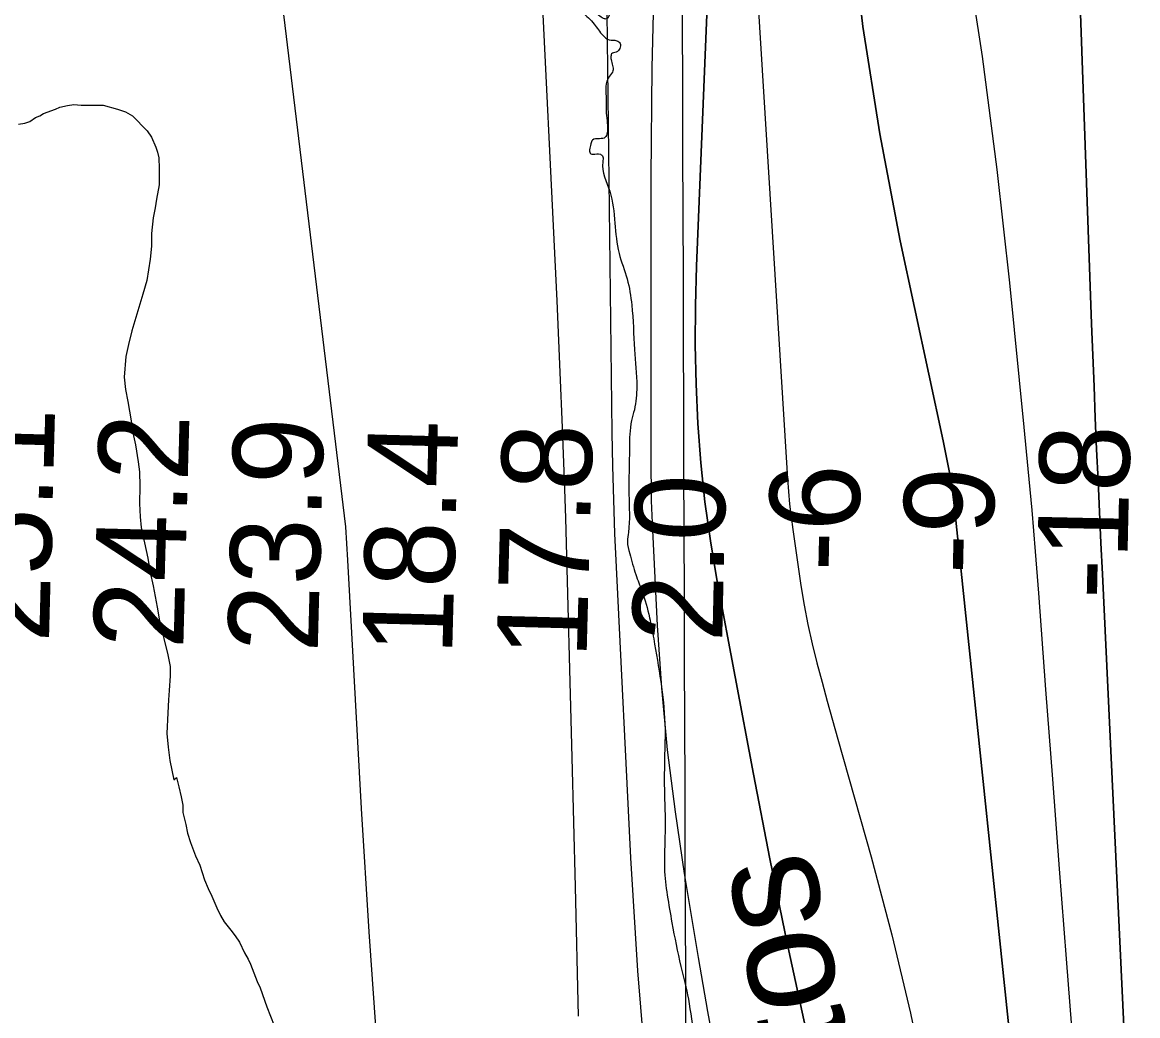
# Model space of a CAD drawing. Extents: x 3392644 to 3430565, y 576657 to 602123.
# Drawn here: x 3401526 to 3402355, y 590935 to 591674 of the extents above; entities that cross this region are included whole.
import ezdxf

# ---------------------------------------------------------------- set-up
doc = ezdxf.new("R2010")
doc.units = 0
for name, color, linetype in [('V-GRID-MAJR', 7, 'Continuous'), ('V-RIVR-EDGE', 7, 'Continuous'), ('V-RIVR-IDEN', 7, 'Continuous'), ('V-RIVR-RANG', 7, 'Continuous'), ('V-SITE-VEGE', 7, 'Continuous'), ('V-TOPO-DPTH', 7, 'Continuous'), ('V-TOPO-MINR', 7, 'Continuous'), ('V-TOPO-WATR', 7, 'Continuous')]:
    doc.layers.add(name, color=color, linetype=linetype)

msp = doc.modelspace()

# ---------------------------------------------------------------- linework, layer by layer
at = {"layer": 'V-GRID-MAJR'}
msp.add_spline([(3402048.6720000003, 582063.4890000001), (3402028.4020000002, 588122.6730000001), (3402008.125, 594183.791), (3401987.849, 600244.93), (3401987.843, 600246.845)], degree=3, dxfattribs=at)
at = {"layer": 'V-RIVR-EDGE'}
msp.add_spline([(3401987.9213314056, 591815.3849305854), (3401986.374240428, 591794.2696732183), (3401984.9403506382, 591784.4067082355), (3401983.8640619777, 591776.657111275), (3401978.9012120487, 591764.6886201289), (3401977.1132064, 591754.1217800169), (3401973.567691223, 591745.3211626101), (3401971.4360255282, 591738.2789260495), (3401969.6454059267, 591726.6549662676), (3401969.2668931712, 591716.0846408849), (3401969.2590513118, 591712.9132818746), (3401968.1827626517, 591705.1636849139), (3401965.688267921, 591693.8938409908), (3401962.838786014, 591681.5677487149), (3401961.7755671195, 591679.1037501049), (3401961.420579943, 591678.0475017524), (3401960.3608463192, 591676.9929960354), (3401957.895105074, 591677.351468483), (3401951.2113409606, 591681.9488754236), (3401944.5240915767, 591685.1367894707), (3401941.7051057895, 591685.1437600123), (3401942.052251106, 591683.0286493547), (3401946.620033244, 591677.7317238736), (3401950.8371847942, 591673.1404161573), (3401957.5113644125, 591664.6669037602), (3401962.0843744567, 591661.4842176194), (3401967.720603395, 591660.7655300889), (3401970.1819880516, 591658.6451915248), (3401967.3473185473, 591652.309444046), (3401963.8201010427, 591650.9086643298), (3401963.465113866, 591649.8524159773), (3401963.457272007, 591646.681056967), (3401964.845853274, 591638.2206143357), (3401962.369656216, 591634.3506081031), (3401959.531501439, 591626.6053677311), (3401959.5245308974, 591623.7863819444), (3401959.849893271, 591612.8619407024), (3401959.83508087, 591606.8715959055), (3401960.503231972, 591592.0701778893), (3401959.085897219, 591588.9023041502), (3401954.8548045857, 591587.8556402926), (3401949.5665922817, 591586.8115903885), (3401948.5025020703, 591583.995218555), (3401948.4842043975, 591576.5953808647), (3401949.8928259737, 591576.2395223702), (3401955.530797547, 591576.2255812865), (3401957.2883070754, 591574.4593585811), (3401957.27872258, 591570.5832531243), (3401962.5102992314, 591548.7230435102), (3401966.3280264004, 591525.1044530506), (3401969.443621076, 591502.5447248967), (3401975.3869147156, 591483.5017584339), (3401978.862724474, 591464.112517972), (3401980.895059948, 591430.9842070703), (3401982.5889632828, 591403.4947390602), (3401980.7844025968, 591386.2328077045), (3401978.650122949, 591378.1334514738), (3401977.190093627, 591357.6992897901), (3401976.752331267, 591323.1675852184), (3401976.330252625, 591294.9785986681), (3401975.6089511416, 591288.2852500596), (3401977.3481629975, 591279.1191896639), (3401981.890676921, 591263.6034407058), (3401986.4410327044, 591251.2590507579), (3401992.0302104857, 591231.5122091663), (3401995.162360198, 591215.6475722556), (3402000.3695399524, 591183.9209123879), (3402003.4642230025, 591152.904226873), (3402003.0177474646, 591114.8487900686), (3402003.616193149, 591071.8575141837), (3402003.1975997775, 591045.0780205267), (3402005.2621740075, 591024.987518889), (3402008.735369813, 591004.5411587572), (3402015.3502998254, 590972.1062671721), (3402020.9281504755, 590947.7785736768), (3402026.4946739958, 590918.8700282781), (3402035.9503727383, 590895.2374967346), (3402040.4928866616, 590879.7217477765), (3402044.68738395, 590865.968736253), (3402045.0005478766, 590850.1110698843), (3402048.467644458, 590827.198097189), (3402058.6080493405, 590795.4592388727), (3402062.094314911, 590780.2984770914), (3402068.73364182, 590757.7300357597), (3402076.0733585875, 590733.3979856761), (3402090.056758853, 590688.2593603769), (3402093.19849306, 590676.2708289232), (3402097.73490776, 590658.2884674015), (3402098.0637554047, 590648.7735190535), (3402100.858344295, 590638.9000982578), (3402105.0606834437, 590628.3184457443)], degree=3, dxfattribs=at)
at = {"layer": 'V-SITE-VEGE'}
for points in [[(3401522.7260000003, 591598.542), (3401527.389, 591599.414), (3401531.129, 591600.7660000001), (3401535.352, 591603.508), (3401538.625, 591604.866), (3401541.4390000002, 591606.691), (3401550.319, 591609.845), (3401553.591, 591611.201), (3401559.193, 591612.53), (3401563.8540000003, 591613.404), (3401569.435, 591612.872), (3401585.72, 591612.675), (3401596.3910000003, 591609.757), (3401602.416, 591607.821), (3401607.501, 591604.968), (3401618.534, 591593.6680000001), (3401621.735, 591588.976), (3401624.903, 591581.49), (3401626.252, 591577.753), (3401627.133, 591573.552), (3401627.504, 591565.637), (3401627.358, 591553.539), (3401625.3680000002, 591542.861), (3401624.358, 591536.356), (3401622.873, 591528.928), (3401621.802, 591517.308), (3401621.6920000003, 591508.002), (3401620.643, 591498.241), (3401618.13, 591482.451), (3401615.2120000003, 591472.248), (3401606.973, 591444.889), (3401604.521, 591434.681), (3401602.555, 591425.863), (3401601.441, 591410.519), (3401602.258, 591401.201), (3401604.0130000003, 591392.339), (3401606.633, 591377.878), (3401607.923, 591369.025), (3401609.676, 591360.161), (3401611.853, 591347.5700000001), (3401612.693, 591340.113), (3401613.031, 591329.406), (3401612.873, 591316.377), (3401613.221, 591306.602), (3401614.057, 591298.68), (3401618.9, 591275.818), (3401620.6350000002, 591265.095), (3401622.843, 591255.295), (3401625.9080000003, 591239.435), (3401627.647, 591229.177), (3401633.861, 591203.9720000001), (3401635.614, 591195.11), (3401635.532, 591188.133), (3401634.938, 591177.432), (3401634.387, 591170.459), (3401633.805, 591160.694), (3401633.154, 591145.344), (3401633.961, 591135.098), (3401635.241, 591125.308), (3401638.325, 591110.845), (3401640.208, 591112.687), (3401641.983, 591105.682), (3401643.757, 591098.215)], [(3401643.757, 591098.215), (3401645.08, 591092.149), (3401645.012, 591086.566), (3401647.232, 591077.697), (3401648.551, 591071.165), (3401650.794, 591064.159), (3401654.398, 591054.343), (3401657.572, 591047.3250000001), (3401661.167, 591036.579), (3401663.878, 591030.029), (3401666.6040000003, 591024.414), (3401670.221, 591015.527), (3401672.9450000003, 591009.91), (3401675.681, 591005.224), (3401680.725, 590999.113), (3401683.932, 590994.888), (3401687.131, 590990.194), (3401690.7600000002, 590982.2390000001), (3401693.4960000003, 590977.553), (3401695.313, 590973.808), (3401700.275, 590960.721), (3401702.5470000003, 590956.039), (3401707.497, 590942.017), (3401712.912, 590927.992)]]:
    msp.add_lwpolyline(points, dxfattribs=at)
at = {"layer": 'V-TOPO-DPTH'}
for points in [[(3402200.914730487, 592946.7586107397), (3402085.380665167, 592338.7008568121), (3402052.7727680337, 592069.1801388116), (3402051.4005930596, 592056.587293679), (3402050.2280213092, 592043.9782718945), (3402049.354854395, 592031.3449851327), (3402048.6812907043, 592018.6955217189), (3402026.940177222, 591493.0218269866), (3402026.170554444, 591463.746747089), (3402025.9881179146, 591434.4768427), (3402026.6864607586, 591405.2147015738), (3402027.971989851, 591375.9577359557), (3402030.2512651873, 591346.7724878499), (3402033.264669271, 591317.6773761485), (3402037.379266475, 591288.7174690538), (3402042.2279924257, 591259.8476983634), (3402069.3611059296, 591115.1590404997), (3402081.620996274, 591052.1971110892), (3402094.4613117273, 590989.3579844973), (3402108.172264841, 590926.7030621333)], [(3402108.172264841, 590926.7030621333), (3402094.4613117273, 590989.3579844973), (3402081.620996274, 591052.1971110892), (3402069.3611059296, 591115.1590404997), (3402042.2279924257, 591259.8476983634), (3402037.379266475, 591288.7174690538), (3402033.264669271, 591317.6773761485), (3402030.2512651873, 591346.7724878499), (3402027.971989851, 591375.9577359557), (3402026.6864607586, 591405.2147015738), (3402025.9881179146, 591434.4768427), (3402026.170554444, 591463.746747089), (3402026.940177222, 591493.0218269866), (3402048.6812907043, 592018.6955217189), (3402049.354854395, 592031.3449851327), (3402050.2280213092, 592043.9782718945), (3402051.4005930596, 592056.587293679), (3402052.7727680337, 592069.1801388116), (3402085.380665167, 592338.7008568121), (3402200.914730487, 592946.7586107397)], [(3402006.5459997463, 592495.9372565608), (3401995.6325773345, 592392.0817369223), (3401964.145147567, 592062.9417480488), (3401963.62457059, 592056.7870882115), (3401963.194334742, 592050.6271157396), (3401962.8996105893, 592044.4591743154), (3401962.695227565, 592038.2859202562), (3401960.711910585, 591948.5655973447), (3401959.843778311, 591897.526860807), (3401959.3223328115, 591846.4863485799), (3401959.3209174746, 591795.4431728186), (3401959.6661889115, 591744.3982213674), (3401964.115790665, 591369.1838692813), (3401964.554176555, 591344.122876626), (3401965.1806947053, 591319.0676487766), (3401966.089411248, 591294.0210681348), (3401967.186260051, 591268.9802522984), (3401977.8742352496, 591052.8318883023), (3401983.2324119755, 590968.6679456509), (3401990.1753502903, 590884.6576055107)], [(3402302.6134252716, 591961.063061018), (3402320.8567761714, 591450.0387901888), (3402321.7186690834, 591426.7553938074), (3402322.6214168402, 591403.4736354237), (3402323.585446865, 591380.1943340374), (3402324.590331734, 591356.9166706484), (3402325.635093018, 591333.640658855), (3402326.6921673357, 591310.3652111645), (3402327.767711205, 591287.0906096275), (3402328.8555681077, 591263.8165721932), (3402355.1042787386, 590706.9785494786)], [(3402355.1042787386, 590706.9785494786), (3402328.8555681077, 591263.8165721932), (3402327.767711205, 591287.0906096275), (3402326.6921673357, 591310.3652111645), (3402325.635093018, 591333.640658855), (3402324.590331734, 591356.9166706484), (3402323.585446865, 591380.1943340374), (3402322.6214168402, 591403.4736354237), (3402321.7186690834, 591426.7553938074), (3402320.8567761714, 591450.0387901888), (3402302.6134252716, 591961.063061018)], [(3402266.7923190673, 590856.0167946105), (3402219.383289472, 591308.7931476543), (3402219.16029798, 591310.8708115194), (3402218.6892060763, 591315.0232906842), (3402218.441105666, 591317.0981059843), (3402217.6872916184, 591323.2664710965), (3402217.019515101, 591328.2719567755), (3402216.2784868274, 591333.2657462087), (3402215.427580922, 591338.2419912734), (3402214.503423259, 591343.2065400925), (3402213.5120709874, 591348.1597933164), (3402212.5044609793, 591353.1096953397), (3402211.472464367, 591358.0545705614), (3402210.4242100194, 591362.9960945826), (3402178.4663359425, 591511.8390599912), (3402163.293924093, 591591.4518484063), (3402150.5984855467, 591671.3993649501), (3402141.618506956, 591751.8489736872)], [(3402266.7923190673, 590856.0167946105), (3402219.383289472, 591308.7931476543), (3402219.16029798, 591310.8708115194), (3402218.6892060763, 591315.0232906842), (3402218.441105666, 591317.0981059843), (3402217.6872916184, 591323.2664710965), (3402217.019515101, 591328.2719567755), (3402216.2784868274, 591333.2657462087), (3402215.427580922, 591338.2419912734), (3402214.503423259, 591343.2065400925), (3402213.5120709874, 591348.1597933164), (3402212.5044609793, 591353.1096953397), (3402211.472464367, 591358.0545705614), (3402210.4242100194, 591362.9960945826), (3402178.4663359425, 591511.8390599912), (3402163.293924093, 591591.4518484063), (3402150.5984855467, 591671.3993649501), (3402141.618506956, 591751.8489736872)]]:
    msp.add_lwpolyline(points, dxfattribs=at)
at = {"layer": 'V-TOPO-MINR'}
for points in [[(3402166.3477562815, 592989.6805613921), (3402023.333321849, 592106.6881891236), (3402019.3003042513, 592076.6578368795), (3402015.7437181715, 592046.5768775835), (3402012.9017793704, 592016.4200077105), (3402010.536272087, 591986.2125307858), (3402003.773892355, 591884.3399300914), (3401999.196925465, 591803.1313316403), (3401995.7015482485, 591721.8870109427), (3401993.828555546, 591640.5891068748), (3401993.0371525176, 591559.2554805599), (3401993.092471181, 591340.1100279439), (3401993.178405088, 591329.2430207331), (3401993.3751991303, 591318.3788706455), (3401993.7382833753, 591307.5190062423), (3401994.212227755, 591296.6619989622), (3401997.8585246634, 591225.6198225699), (3402001.02583153, 591179.3292255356), (3402005.2396910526, 591133.1521294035), (3402011.0233795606, 591087.1452846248), (3402017.8536207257, 591041.251940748), (3402028.254734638, 590978.702703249), (3402035.2523009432, 590938.4310933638), (3402042.638547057, 590898.2338251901)], [(3402006.5459997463, 592495.9372565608), (3401995.6325773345, 592392.0817369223), (3401964.145147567, 592062.9417480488), (3401963.62457059, 592056.7870882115), (3401963.194334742, 592050.6271157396), (3401962.8996105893, 592044.4591743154), (3401962.695227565, 592038.2859202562), (3401960.711910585, 591948.5655973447), (3401959.843778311, 591897.526860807), (3401959.3223328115, 591846.4863485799), (3401959.3209174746, 591795.4431728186), (3401959.6661889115, 591744.3982213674), (3401964.115790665, 591369.1838692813), (3401964.554176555, 591344.122876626), (3401965.1806947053, 591319.0676487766), (3401966.089411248, 591294.0210681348), (3401967.186260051, 591268.9802522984), (3401977.8742352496, 591052.8318883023), (3401983.2324119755, 590968.6679456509), (3401990.1753502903, 590884.6576055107)], [(3401675.8207681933, 592029.1044409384), (3401676.406682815, 592025.2731897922), (3401676.5253450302, 592024.6206556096), (3401677.980705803, 592016.4691087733), (3401679.401175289, 592008.3116014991), (3401680.7693078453, 592000.1451535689), (3401682.1025491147, 591991.9727452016), (3401765.8551486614, 591299.0722258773), (3401767.3352383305, 591274.288312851), (3401777.6937299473, 591089.6539216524), (3401783.3508998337, 590997.885167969), (3401789.683309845, 590906.1667832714)], [(3401896.8283169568, 592004.9982508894), (3401923.1078588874, 591467.2142838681), (3401924.442691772, 591437.7584688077), (3401925.6859397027, 591408.2986460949), (3401926.868130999, 591378.8361516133), (3401928.5903850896, 591334.1815834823), (3401928.8526208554, 591327.0439458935), (3401929.0974771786, 591319.9057439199), (3401929.316264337, 591312.7666953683), (3401929.517672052, 591305.6270824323), (3401934.2166814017, 591127.5169230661), (3401936.680185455, 591031.3200367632), (3401939.044525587, 590935.1207899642)], [(3402302.6134252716, 591961.063061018), (3402320.8567761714, 591450.0387901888), (3402321.7186690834, 591426.7553938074), (3402322.6214168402, 591403.4736354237), (3402323.585446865, 591380.1943340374), (3402324.590331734, 591356.9166706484), (3402325.635093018, 591333.640658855), (3402326.6921673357, 591310.3652111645), (3402327.767711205, 591287.0906096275), (3402328.8555681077, 591263.8165721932), (3402355.1042787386, 590706.9785494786)], [(3402066.314073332, 591791.0766759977), (3402094.6532840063, 591334.8446766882), (3402095.357867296, 591325.3870916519), (3402096.217392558, 591315.9455394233), (3402097.3093307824, 591306.528036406), (3402098.55621098, 591297.1265661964), (3402104.615588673, 591255.3924102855), (3402106.989970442, 591240.8788731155), (3402109.709146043, 591226.4366919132), (3402112.945512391, 591212.101544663), (3402116.526672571, 591197.8377533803), (3402120.3902417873, 591183.6340001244), (3402124.284529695, 591169.4387277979), (3402128.224895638, 591155.2561768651), (3402132.1959802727, 591141.0821068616), (3402156.8271223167, 591053.7120508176), (3402172.1772098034, 590995.6444052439), (3402186.2509795, 590937.2909226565), (3402198.410272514, 590878.5086845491)], [(3402141.618506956, 591751.8489736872), (3402150.5984855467, 591671.3993649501), (3402163.293924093, 591591.4518484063), (3402178.4663359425, 591511.8390599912), (3402210.4242100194, 591362.9960945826), (3402211.472464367, 591358.0545705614), (3402212.5044609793, 591353.1096953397), (3402213.5120709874, 591348.1597933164), (3402214.503423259, 591343.2065400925), (3402215.427580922, 591338.2419912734), (3402216.2784868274, 591333.2657462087), (3402217.019515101, 591328.2719567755), (3402217.6872916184, 591323.2664710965), (3402218.441105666, 591317.0981059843), (3402218.6892060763, 591315.0232906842), (3402219.16029798, 591310.8708115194), (3402219.383289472, 591308.7931476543), (3402266.7923190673, 590856.0167946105)], [(3402226.428971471, 591732.9130582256), (3402239.400671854, 591649.0591442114), (3402250.280920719, 591564.9083029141), (3402259.7668685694, 591480.5595100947), (3402270.4937692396, 591373.1503454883), (3402273.453070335, 591342.3473431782), (3402276.2577657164, 591311.530855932), (3402278.830552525, 591280.6941412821), (3402281.2487336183, 591249.8439416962), (3402286.604579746, 591178.0507601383), (3402291.6250183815, 591111.2969430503), (3402296.699195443, 591044.5472436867), (3402301.853980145, 590977.8037209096), (3402307.062503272, 590911.0643158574)]]:
    msp.add_lwpolyline(points, dxfattribs=at)
at = {"layer": 'V-TOPO-WATR'}
msp.add_lwpolyline([(3402200.914730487, 592946.7586107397), (3402085.380665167, 592338.7008568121), (3402052.7727680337, 592069.1801388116), (3402051.4005930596, 592056.587293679), (3402050.2280213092, 592043.9782718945), (3402049.354854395, 592031.3449851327), (3402048.6812907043, 592018.6955217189), (3402026.940177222, 591493.0218269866), (3402026.170554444, 591463.746747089), (3402025.9881179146, 591434.4768427), (3402026.6864607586, 591405.2147015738), (3402027.971989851, 591375.9577359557), (3402030.2512651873, 591346.7724878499), (3402033.264669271, 591317.6773761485), (3402037.379266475, 591288.7174690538), (3402042.2279924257, 591259.8476983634), (3402069.3611059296, 591115.1590404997), (3402081.620996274, 591052.1971110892), (3402094.4613117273, 590989.3579844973), (3402108.172264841, 590926.7030621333)], dxfattribs=at)

# ---------------------------------------------------------------- texts
at = {"layer": 'V-RIVR-IDEN'}
msp.add_text('Photos', height=83, rotation=101.0107529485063, dxfattribs=at).set_placement((3402178.038564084, 590721.1296090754))
at = {"layer": 'V-RIVR-RANG'}
for s, height, rotation, p in [('25.1', 67, 88.47832571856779, (3401545.370116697, 591212.6836548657)), ('24.2', 67, 88.47832571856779, (3401645.2780744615, 591207.9094763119)), ('23.9', 67, 88.47832571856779, (3401745.2430697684, 591205.2447898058)), ('18.4', 67, 88.47832571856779, (3401845.2210744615, 591203.1064763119)), ('17.8', 67, 88.47832571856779, (3401945.1920744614, 591200.705476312)), ('-18', 67.00000000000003, 88.76577777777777, (3402346.8298482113, 591244.7899967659)), ('-6', 67.00000000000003, 88.76577777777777, (3402147.227750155, 591265.4150965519)), ('2.0', 67.00000000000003, 88.76577777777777, (3402046.0749567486, 591212.9626839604)), ('-9', 67.00000000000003, 88.76577777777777, (3402247.204431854, 591263.2778148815))]:
    msp.add_text(s, height=height, rotation=rotation, dxfattribs=at).set_placement(p)

doc.saveas('drawing.dxf')
